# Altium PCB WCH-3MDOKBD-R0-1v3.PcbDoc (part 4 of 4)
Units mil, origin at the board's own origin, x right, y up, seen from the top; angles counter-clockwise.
Board outline 11710.74 x 4477.49 mil, 2 copper layers (Top Layer, Bottom Layer); 233 components, 145 nets, 545 pads, 1448 vias.
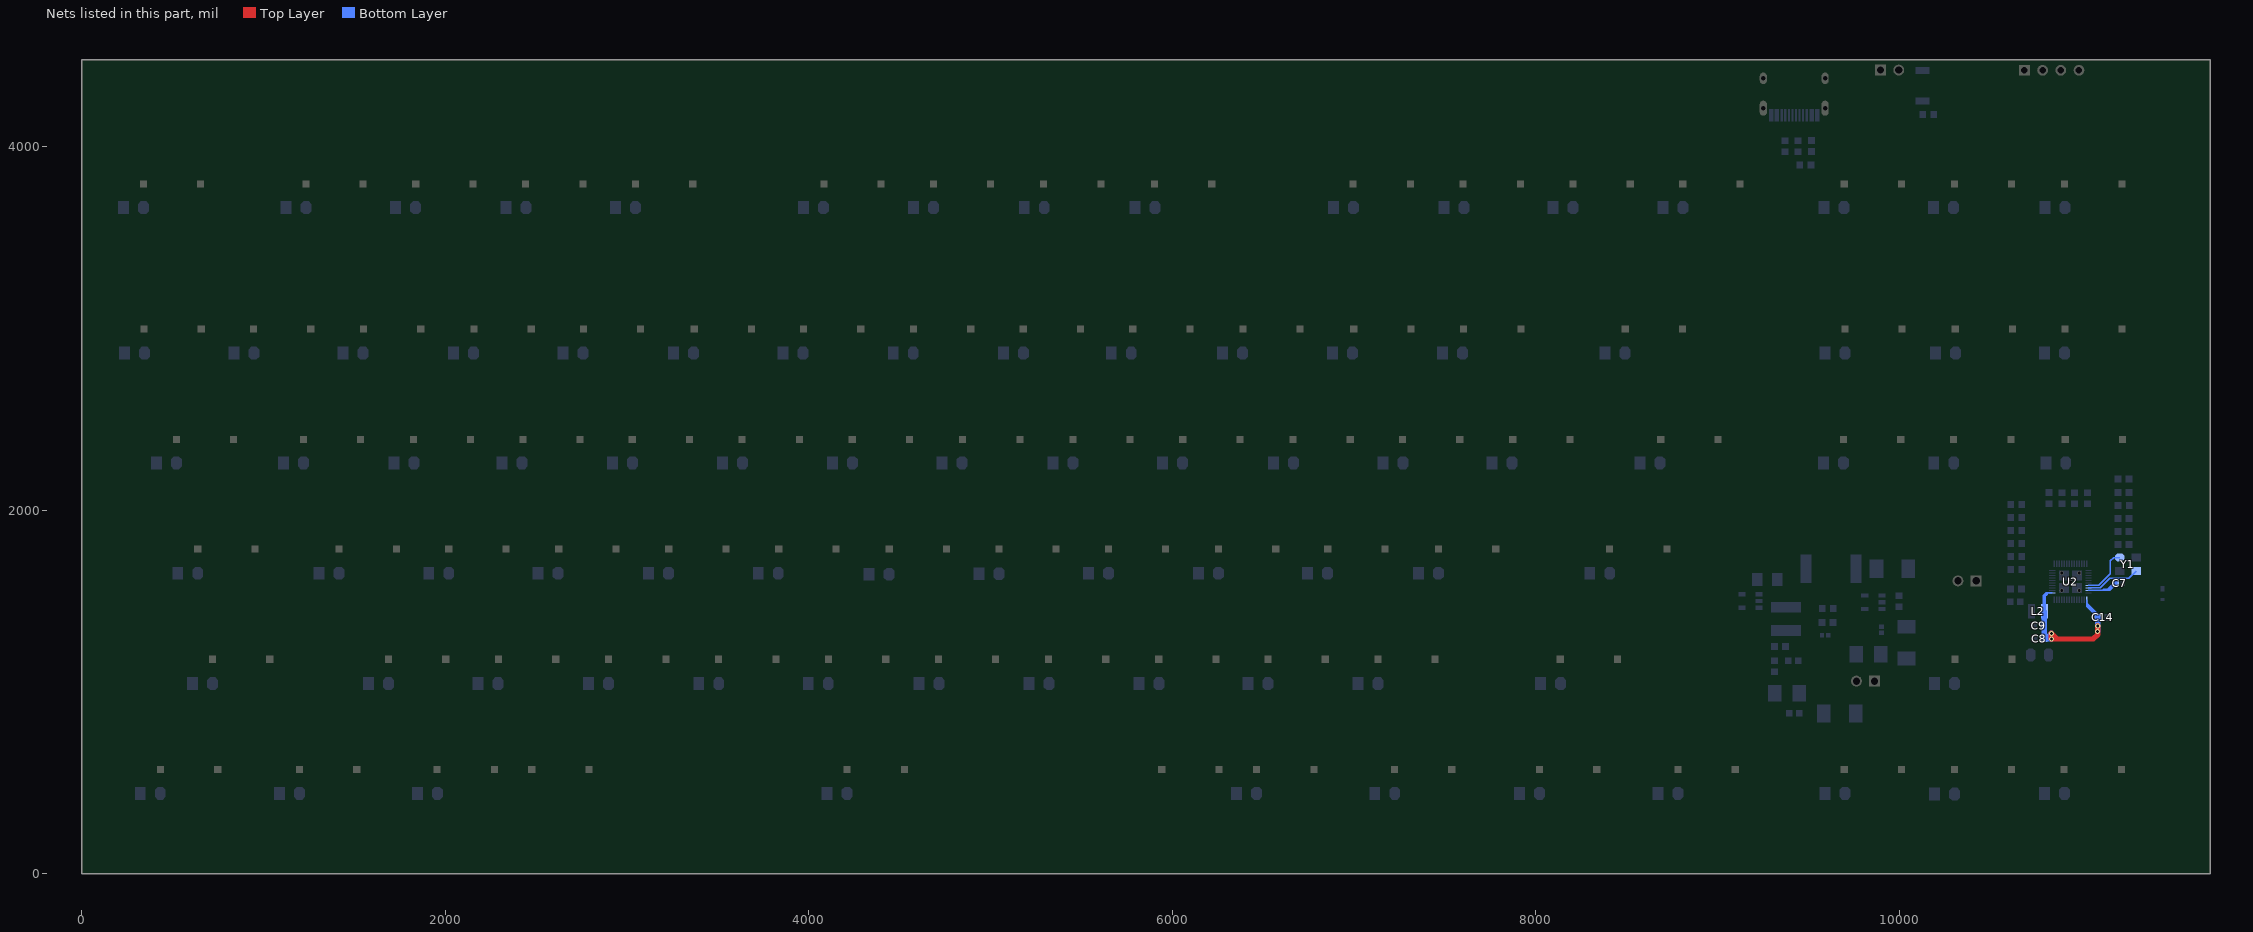
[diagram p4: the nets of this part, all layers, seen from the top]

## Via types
v1: diameter 28, hole 16, Top Layer to Bottom Layer, tented both sides, 1320 vias
v2: diameter 24, hole 12, Top Layer to Bottom Layer, tented both sides, 128 vias

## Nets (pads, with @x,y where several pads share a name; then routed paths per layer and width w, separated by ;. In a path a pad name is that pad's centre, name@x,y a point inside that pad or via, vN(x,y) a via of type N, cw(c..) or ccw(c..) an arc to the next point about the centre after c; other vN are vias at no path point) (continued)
VDCIA: C8.2 C9.2 C14.2 L2.2 U2.1 U2.35 | length 1443.6
  Top Layer w30: v1@11091.5,1363.19 11091.5,1316.25 11065.95,1290.7 10866.43,1290.7 ; 10866.43,1290.7 v1(10836.12,1321.01) v1(10836.12,1290.7) 10866.43,1290.7
  Bottom Layer w7: L2.2@10795.4,1441.07 L2.2@10797.66,1443.33 ; U2.1@10841.57,1543.71 10818.58,1543.71 ; U2.35@11030.55,1506.72 11030.55,1486.84 ; C14.2@11087.52,1412.47 11030.55,1469.45 ; C14.2@11091.5,1405.85 11091.5,1408.5 C14.2@11091.5,1417.84 ; C14.2@11092.82,1407.17 11092.82,1416.52 C14.2@11091.5,1417.84 ; L2.2@10797.66,1443.33 10802.62,1448.29 10802.62,1527.74 ; L2.2@10797.66,1443.33 10797.66,1522.78 ; L2.2@10797.66,1443.33 10791.56,1449.42 10791.56,1527.97 10797.66,1534.06 ; 10797.66,1522.78 10802.62,1527.74 ; 10797.66,1522.78 10797.66,1534.06 ; 10797.66,1534.06 10805.66,1534.06 10807.3,1532.42 ; 10797.66,1534.06 10807.3,1543.71 ; 10802.62,1527.74 10807.3,1532.42 ; 10807.3,1532.42 10818.58,1543.71 ; 10807.3,1532.42 10807.3,1543.71 ; 10807.3,1543.71 10818.58,1543.71 ; 11030.55,1469.45 11030.55,1478.79 ; 11030.55,1469.45 11039.89,1469.45 ; 11030.55,1478.79 11030.55,1486.84 ; 11030.55,1478.79 11038.6,1478.79 ; 11030.55,1478.79 11039.89,1469.45 ; 11030.55,1486.84 11038.6,1478.79 ; 11038.6,1478.79 11091.5,1425.89 C14.2@11091.5,1417.84 ; 11039.89,1469.45 C14.2@11091.5,1417.84
  Bottom Layer w30: C8.2@10795.4,1292.32 L2.2@10795.4,1441.07 ; C8.2@10796.11,1292.32 C8.2@10807.43,1292.32 ; C14.2@11087.52,1412.47 11091.5,1408.5 11092.82,1407.17 11091.5,1405.85 v1@11091.5,1332.25 ; C8.2@10807.43,1292.32 v1(10836.12,1321.01) v1(10836.12,1290.7) 10834.51,1292.32 C8.2@10807.43,1292.32
  other v1: 11090.44,1332.25 11090.93,1363.19
VINTA: C7.2 U2.33 | length 363.4
  Bottom Layer w7: U2.33@11039.89,1557.49 11118.9,1557.49 ; 11118.9,1557.49 11140.02,1557.49 ; 11118.9,1557.49 11124.61,1563.19 11145.72,1563.19 ; 11140.02,1557.49 11145.72,1563.19 ; 11140.02,1557.49 11148.24,1557.49 ; 11145.72,1563.19 11178.59,1596.06 ; 11148.24,1557.49 C7.2@11186.81,1596.06 ; 11148.24,1557.49 11156.24,1557.49 C7.2@11194.81,1596.06 ; 11178.59,1596.06 11187.11,1604.58 C7.2@11190.66,1604.58 ; 11178.59,1596.06 C7.2@11186.81,1596.06 ; C7.2@11186.81,1596.06 11190.66,1599.91 C7.2@11190.66,1604.58 ; C7.2@11186.81,1596.06 C7.2@11194.81,1596.06 ; C7.2@11190.66,1604.58 11194.22,1604.58 11194.22,1596.65 C7.2@11194.81,1596.06
X32MI: U2.32 Y1.3 | length 300.3
  Bottom Layer w7: U2.32@11039.89,1571.27 11105.25,1571.27 11158.07,1624.09 11262.24,1624.09 Y1.3@11301.9,1663.76
X32MO: U2.31 Y1.1 | length 277.6
  Bottom Layer w7: U2.31@11039.89,1585.05 11096.86,1585.05 11160.34,1648.53 11160.34,1721.23 11177.67,1738.56 Y1.1@11211.35,1738.56
pads on no net: P9.A8 P9.B8 S88.1 S88.2 S89.1 S89.2 U1.3

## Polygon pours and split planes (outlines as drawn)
BT- on Bottom Layer "GND" (hatched Horizontal grid 8 track 8, remove dead copper, pour order 1): 11710.74,4477.49 11710.74,0 0,0 0,4477.49
BT- on Bottom Layer "GND1" (hatched Horizontal grid 8 track 8, remove dead copper, pour order 3): 11013.8,1575.74 11013.8,1440.99 11441.92,1440.99 11441.92,1582.06
BT- on Top Layer "GND" (hatched Horizontal grid 8 track 8, remove dead copper, pour order 0): 0,4477.49 0,0 11710.74,0 11710.74,4477.49

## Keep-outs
Keep-Out Layer:
  lines w8: 0,0 11710.66,0 11710.66,4477.97 0,4477.97 0,0

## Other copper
Top Layer:
  rectangle net BT-: 10871.04,1534.94 11010.24,1676.49
Bottom Layer:
  rectangle net BT-: 11373.76,1548.89 11446.6,1584.33
  rectangle net BT-: 11404.52,1529.19 11434.63,1606.16
  region net BT-: 11425.68,1527.03 11425.68,1642.44 11383.11,1642.44 11383.11,1527.03
  pour cut-out: 9285.18,1302.37 9465.95,1302.37 9465.95,1493.79 9285.18,1493.79
  pour cut-out: 9453.32,1768.79 9453.32,1582.84 9796.7,1582.84 9796.7,1768.79
Multi-Layer:
  pour cut-out: 11711.79,4477.49 11430.63,4477.49 11430.63,0 11711.79,0

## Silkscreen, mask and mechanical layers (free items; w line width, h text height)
Top Overlay:
  drawing of 379 lines, arcs and shapes, not listed
  text "预留I2C" at 10758.08,4268.78 h60
  text "WCH-3MODEKBD-R0-1v3" at 9286.34,1929.11 h60
Bottom Overlay:
  lines w10: 9391.94,3897.72 9411.03,3916.8 9411.03,3941.59
  text "SDA" at 10880.68,4257.28 h35 r270
  text "SCL" at 10780.3,4254.46 h35 r270
  text "UD+" at 9977.79,4251.81 h35 r270
  text "BT-" at 10973.47,4251.59 h35 r270
  text "+3V3" at 10665.12,4218.55 h35 r270
  text "+3V3" at 9870.48,4217.62 h35 r270
  text "BT-" at 10300.76,1440.38 h35 r270
  text "TXD1" at 10408.21,1425.04 h35 r270
  text "BT+" at 9774.21,959.35 h35
  text "BT-" at 9905.62,957.49 h35
Mechanical 1:
  the board outline again, w10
